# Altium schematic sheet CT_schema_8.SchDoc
size 423 x 414 mm
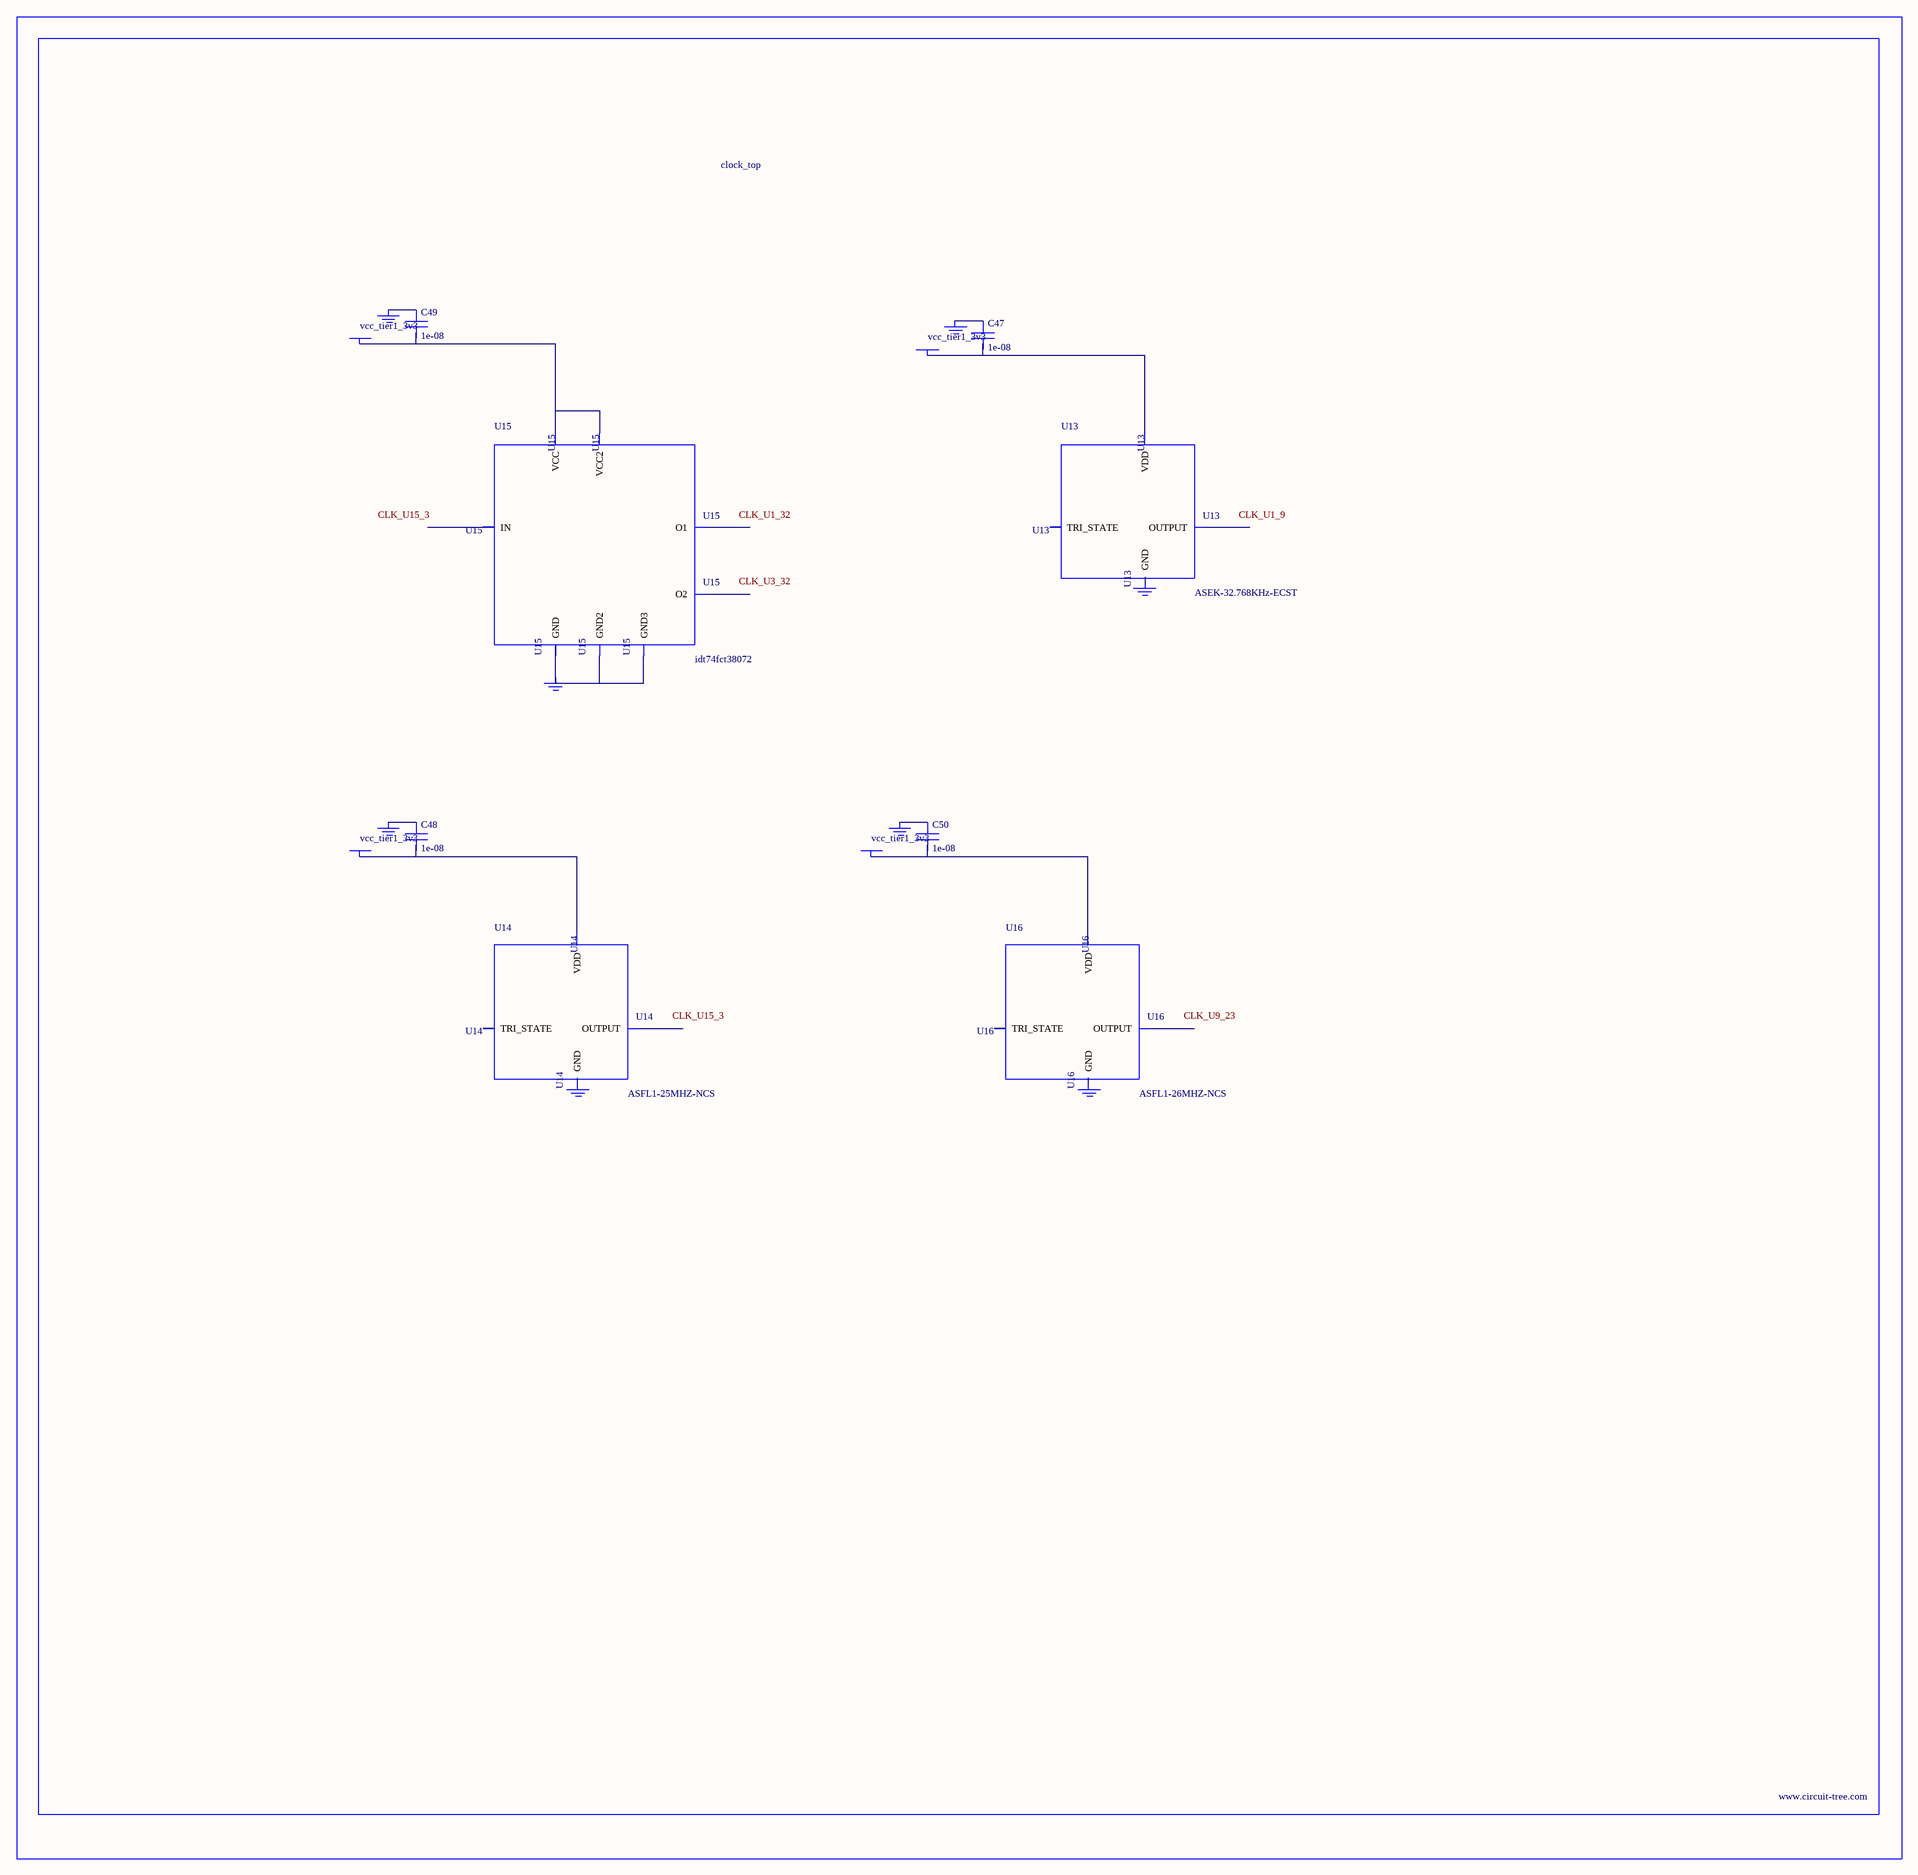
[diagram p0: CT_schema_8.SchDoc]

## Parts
BORDER7  (no value)
C47  1e-08  [C0402]
C48  1e-08  [C0402]
C49  1e-08  [C0402]
C50  1e-08  [C0402]
GND_INSTANCE_7_0  (no value)
GND_INSTANCE_7_1  (no value)
GND_INSTANCE_7_2  (no value)
GND_INSTANCE_7_3  (no value)
GND_INSTANCE_7_4  (no value)
GND_INSTANCE_7_5  (no value)
GND_INSTANCE_7_6  (no value)
GND_INSTANCE_7_7  (no value)
POWER_INSTANCE_7_0  vcc_tier1_3v3
POWER_INSTANCE_7_1  vcc_tier1_3v3
POWER_INSTANCE_7_2  vcc_tier1_3v3
POWER_INSTANCE_7_3  vcc_tier1_3v3
U13  ASEK-32.768KHz-ECST  [ASEK]
U14  ASFL1-25MHZ-NCS  [ASFL1]
U15  idt74fct38072  [IDT74FCT38072]
U16  ASFL1-26MHZ-NCS  [ASFL1]

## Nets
NetC47_1: C47.1 GND_INSTANCE_7_0.0(GND)
NetC47_2: C47.2 POWER_INSTANCE_7_0.0(PWR) U13.4(VDD)
NetC48_1: C48.1 GND_INSTANCE_7_2.0(GND)
NetC48_2: C48.2 POWER_INSTANCE_7_1.0(PWR) U14.4(VDD)
NetC49_1: C49.1 GND_INSTANCE_7_4.0(GND)
NetC49_2: C49.2 POWER_INSTANCE_7_2.0(PWR) U15.1(VCC) U15.2(VCC2)
NetC50_1: C50.1 GND_INSTANCE_7_6.0(GND)
NetC50_2: C50.2 POWER_INSTANCE_7_3.0(PWR) U16.4(VDD)
NetGND_INSTANCE_7_5_0: GND_INSTANCE_7_5.0(GND) U15.4(GND) U15.5(GND2) U15.8(GND3)

Not connected (* = marked no-connect by the designer): GND_INSTANCE_7_1 0(GND); GND_INSTANCE_7_3 0(GND); GND_INSTANCE_7_7 0(GND); U13 1(TRI_STATE) 2(GND) 3(OUTPUT); U14 1(TRI_STATE) 2(GND) 3(OUTPUT); U15 3(IN) 6(O2) 7(O1); U16 1(TRI_STATE) 2(GND) 3(OUTPUT)

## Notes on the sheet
- Labels drawn without touching a wire or pin: CLK_U1_9, CLK_U1_32, CLK_U3_32, CLK_U9_23, CLK_U15_3

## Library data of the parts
BORDER7 = BORDER_PAGE7
C47-C50 = C0402C103K3RAC
GND_INSTANCE_7_0-GND_INSTANCE_7_7 = GND
POWER_INSTANCE_7_0-POWER_INSTANCE_7_3 = PWR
